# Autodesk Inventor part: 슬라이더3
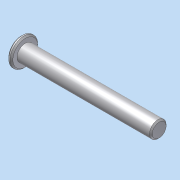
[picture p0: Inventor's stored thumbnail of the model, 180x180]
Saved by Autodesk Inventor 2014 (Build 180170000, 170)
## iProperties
Company: 한국ATC센터
Created: 2015-04
Part Number: 슬라이더3
Document SubType Name: Modeling
Designer: KYOUNG IL JANG
Density: 1 g/cm^3
Material: 일반
Mass: 11.8344 g
Surface Area: 43.7403 cm^2
Volume: 11.8344 cm^3
Appearance: 기본값
Author: KYOUNG IL JANG
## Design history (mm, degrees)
sketch "스케치1"
  geometry: L1 (0, 0)-(0, 10); L2 (0, 10)-(-3, 10); L3 (-3, 10)-(-3, 6); L4 (-3, 6)-(-100, 6); L5 (-100, 6)-(-100, 0); L6 (-100, 0)-(0, 0)
  constraints: 12 end point, 4 parallel, 1 perpendicular, 1 vertical
  dimensions: "d0" = 12 diameter of L4 L6; "d1" = 20 diameter of L2 L6; "d2" = 3 distance between parallel lines of L3 L1; "d3" = 100 distance between parallel lines of L5 L1
revolve "회전1" sketch "스케치1" stored, may be unused: angle "d4" = 90 deg
chamfer "모따기1" distance "d5" = 1; stored, may be unused: second distance "d6" = 2, angle "d7" = 45 deg
node "솔리드1"
